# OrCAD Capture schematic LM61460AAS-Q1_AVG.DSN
size D; title: LM61460-Q1 Automotive 3-V to 36-V, 6-A, Low EMI; rev: 1.0; note: Datasheet: SNVSB70E                EVM: SNVU621C; note: Synchronous Step Down Converter; note: Synchronous  Step-Down Converter
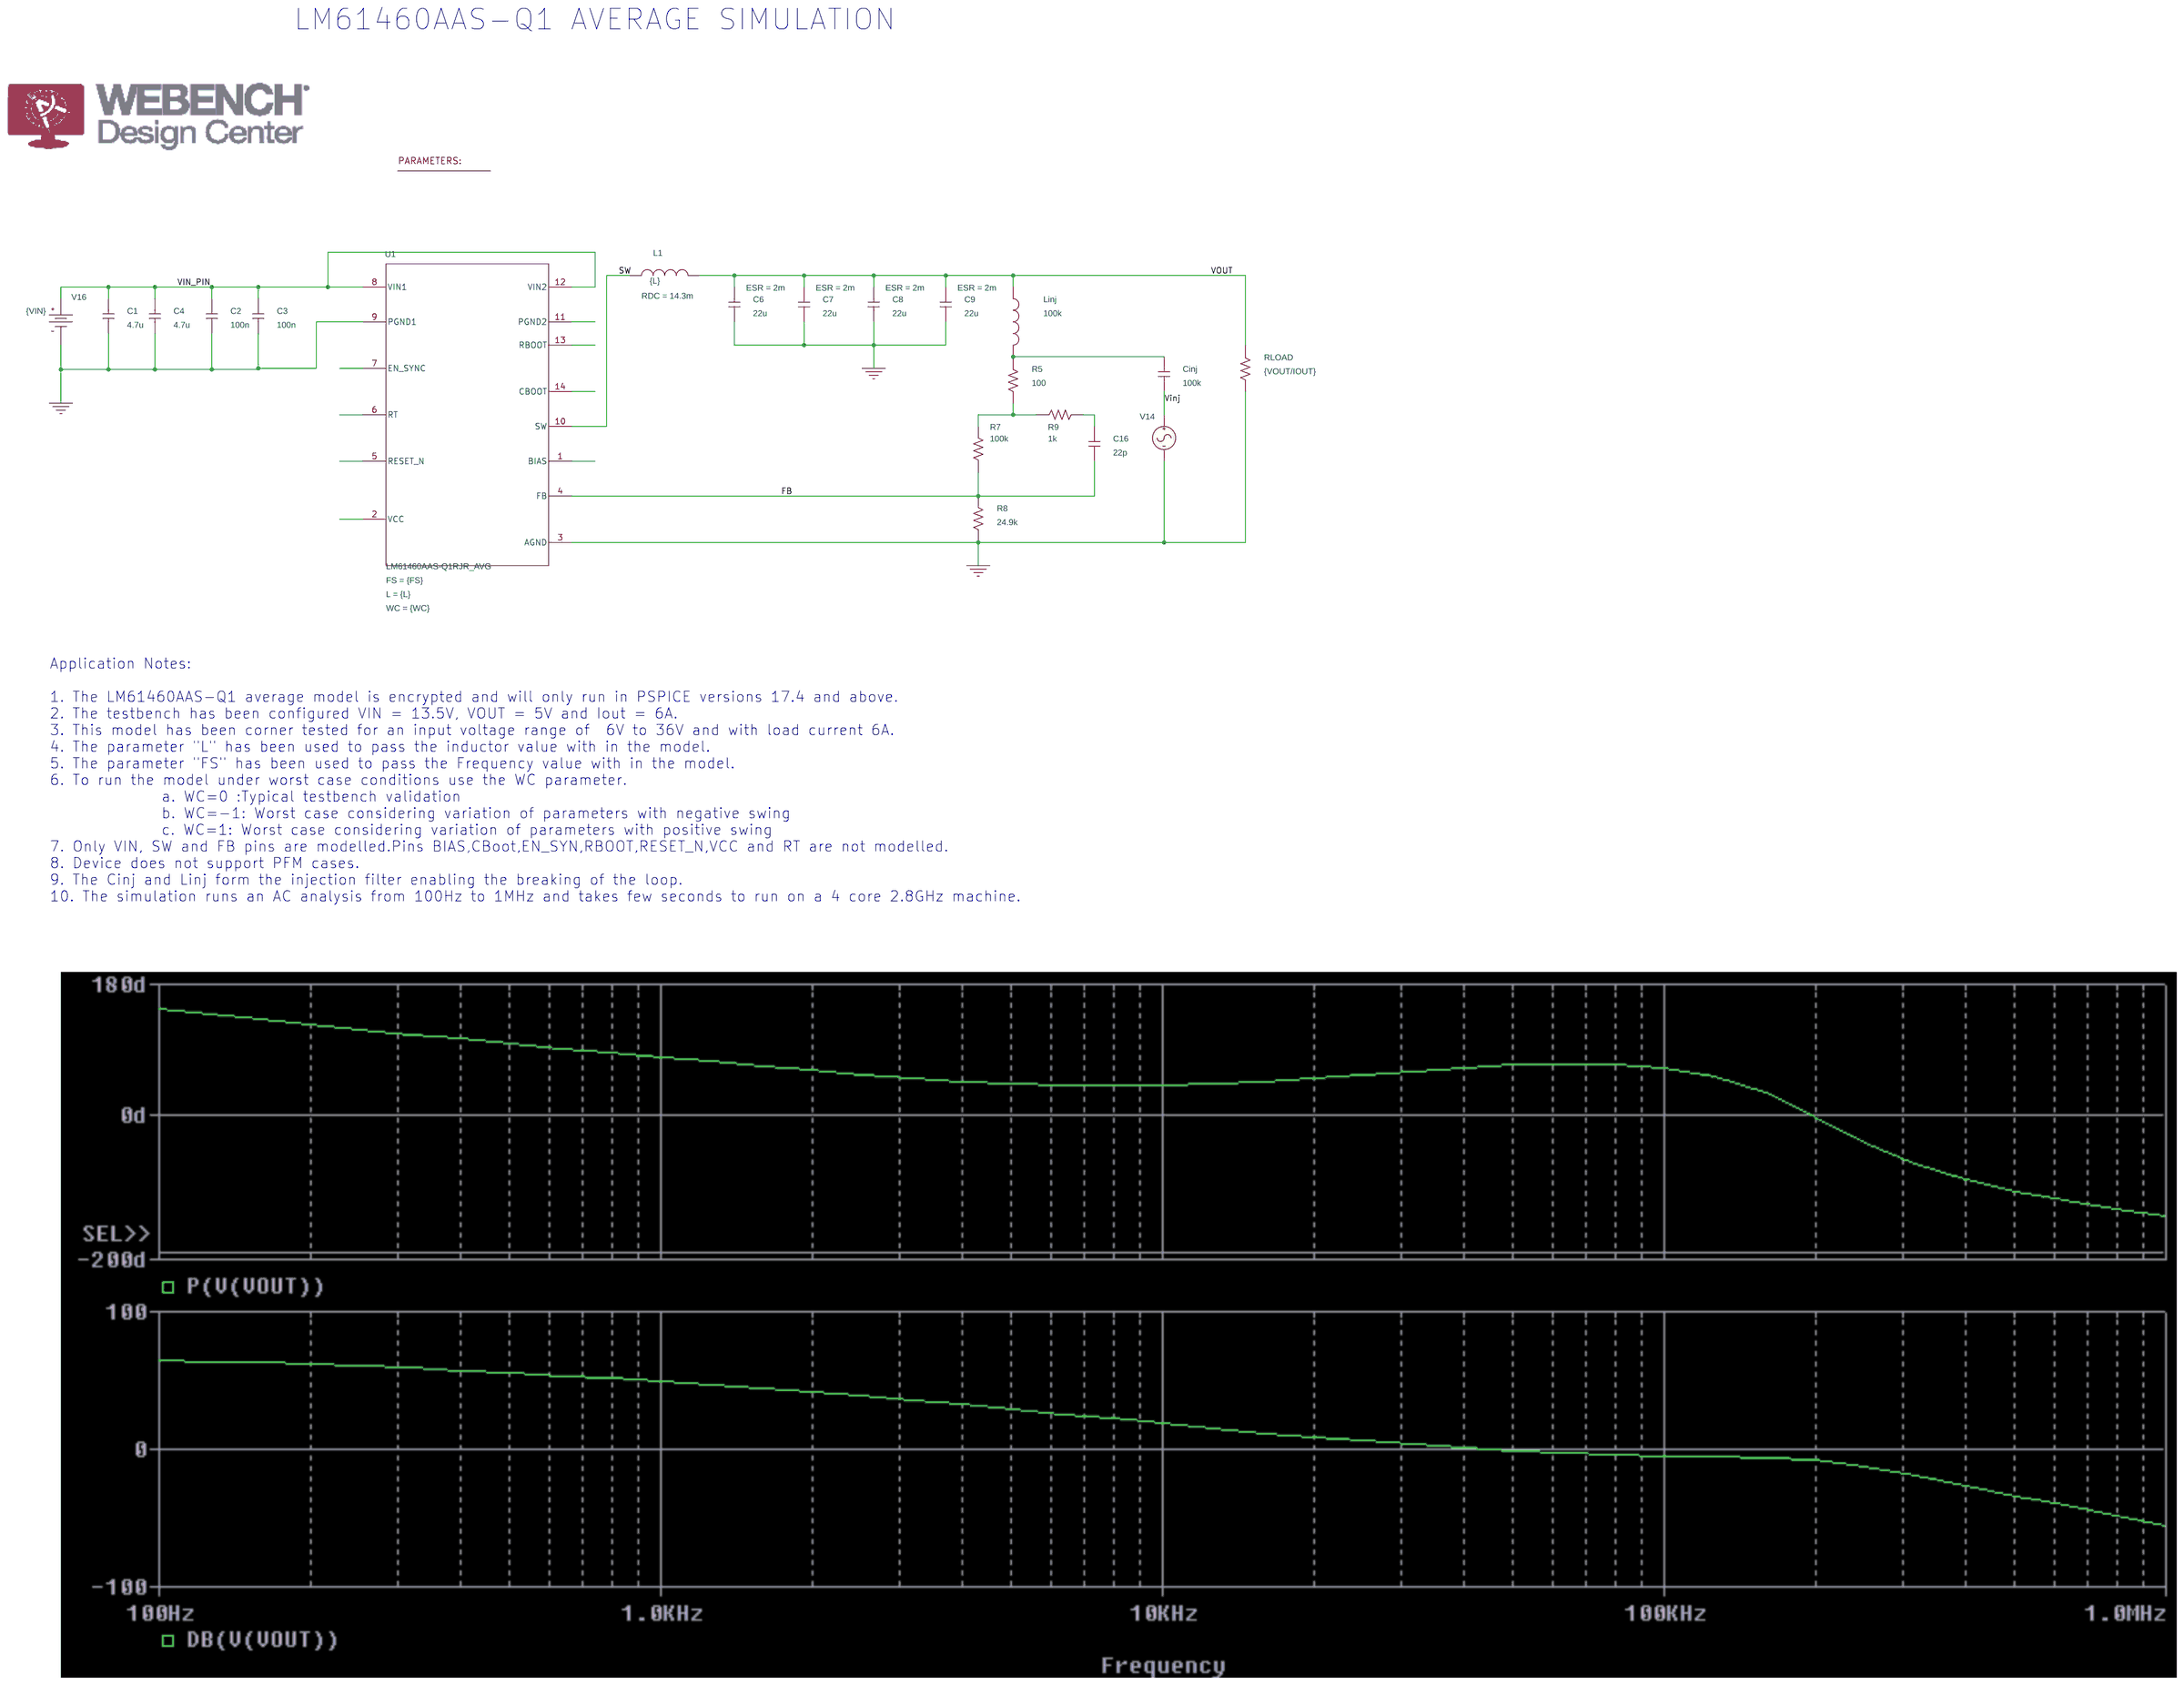
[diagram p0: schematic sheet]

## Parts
2  PARAM
C1  4.7u  [RAD/CK05]
C2  100n  [RAD/CK05]
C3  100n  [RAD/CK05]
C4  4.7u  [RAD/CK05]
C6  22u  [RAD/CK05]
C7  22u  [RAD/CK05]
C8  22u  [RAD/CK05]
C9  22u  [RAD/CK05]
C16  22p  [RAD/CK05]
Cinj  100k  [RAD/CK05]
L1  {L}  [DISC/.350x.175/LS.200x.100/.034]
Linj  100k  [DISC/.350x.175/LS.200x.100/.034]
R5  100  [AX/RC05]
R7  100k  [AX/RC05]
R8  24.9k  [AX/RC05]
R9  1k  [AX/RC05]
RLOAD  {VOUT/IOUT}  [AX/RC05]
U1  LM61460AAS-Q1RJR_AVG  [RJR0014A]
V14  VAC
V16  VDC

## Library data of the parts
2 = PARAM: FS: 400k; IOUT: 6; L: 4.7u; VIN: 13.5; VOUT: 5; WC: 0
C1-C4 C16 Cinj = C
C6-C9 = C: AppProp: InductiveSlave:;SRF:;PrevCap:22u;PrevESL:; ESR: 2m
L1 = L: AppProp: SRF:; RDC: 14.3m
Linj = L
R5 R7-R9 RLOAD = R
U1 = LM61460AAS-Q1RJR_AVG: FS: {FS}; L: {L}; WC: {WC}
V14 = VAC
V16 = VDC: DC: {VIN}

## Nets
VIN_PIN: C1.1 C2.1 C3.1 C4.1 U1.8(VIN1) U1.12(VIN2) V16.0(+)
Vinj: Cinj.2 V14.1(+)
0: C1.2 C2.2 C3.2 C4.2 C6.2 C7.2 C8.2 C9.2 R8.1 RLOAD.2 U1.3(AGND) U1.9(PGND1) V14.2(-) V16.1(-)
FB: C16.2 R7.1 R8.2 U1.4(FB)
SW: L1.1 U1.10(SW)
VOUT: C6.1 C7.1 C8.1 C9.1 L1.2 Linj.1 RLOAD.1
N16791817: Cinj.1 Linj.2 R5.1
N16791927: R5.2 R7.2 R9.1
N16793426: C16.1 R9.2

Not connected (* = marked no-connect by the designer): U1 1(BIAS) 2(VCC) 5(RESET_N) 6(RT) 7(EN_SYNC) 11(PGND2) 13(RBOOT) 14(CBOOT)

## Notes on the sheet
- LM61460AAS-Q1 AVERAGE SIMULATION
- Application Notes:
  1. The LM61460AAS-Q1 average model is encrypted and will only run in PSPICE versions 17.4 and above.
  2. The testbench has been configured VIN = 13.5V, VOUT = 5V and Iout = 6A.
  3. This model has been corner tested for an input voltage range of  6V to 36V and with load current 6A.
  4. The parameter "L" has been used to pass the inductor value with in the model.
  5. The parameter "FS" has been used to pass the Frequency value with in the model.
  6. To run the model under worst case conditions use the WC parameter.
  		    a. WC=0 :Typical testbench validation
  		    b. WC=-1: Worst case considering variation of parameters with negative swing
  		    c. WC=1: Worst case considering variation of parameters with positive swing
  7. Only VIN, SW and FB pins are modelled.Pins BIAS,CBoot,EN_SYN,RBOOT,RESET_N,VCC and RT are not modelled.
  8. Device does not support PFM cases.
  9. The Cinj and Linj form the injection filter enabling the breaking of the loop.
  10. The simulation runs an AC analysis from 100Hz to 1MHz and takes few seconds to run on a 4 core 2.8GHz machine.
